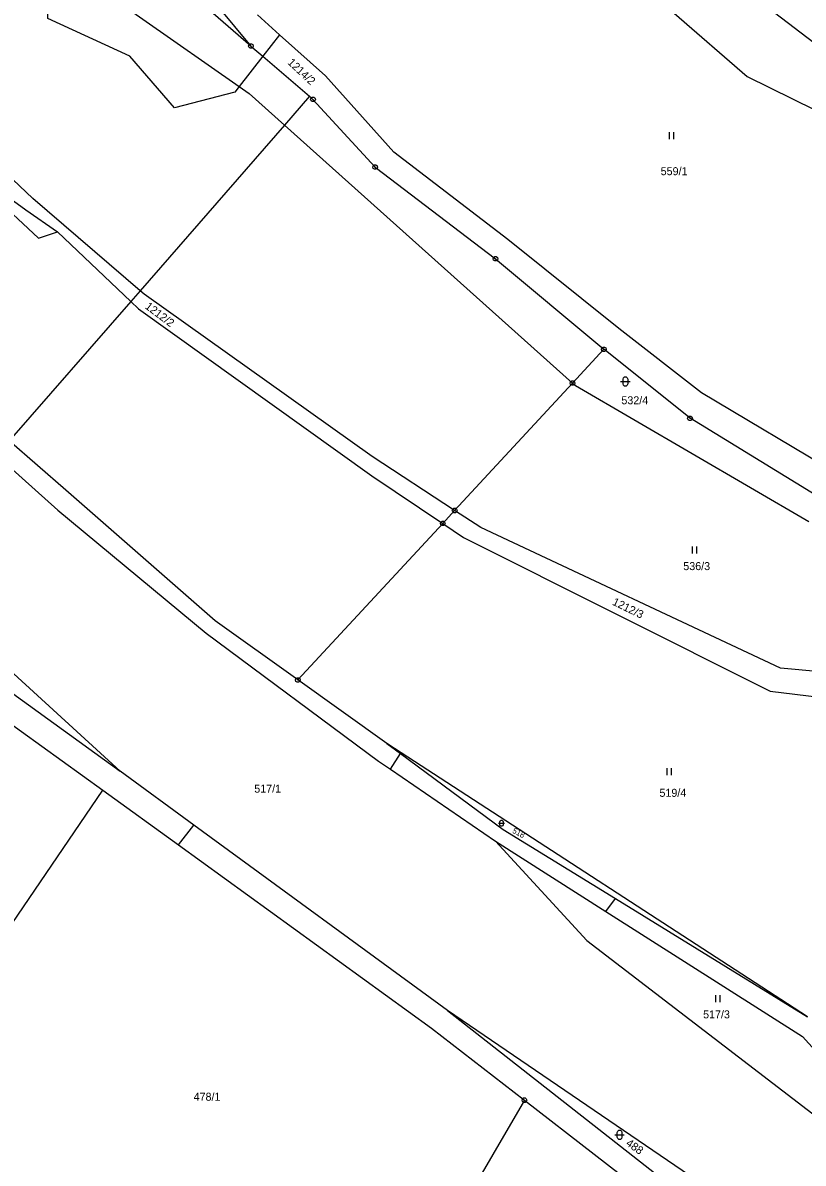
# Model space of a CAD drawing. Extents: x -694465 to -690527, y -983694 to -978978.
# Drawn here: x -692006.8 to -691841.2, y -980787.1 to -980544.9 of the extents above; entities that cross this region are included whole.
import ezdxf

# ---------------------------------------------------------------- set-up
doc = ezdxf.new("R2010")
doc.units = 0
for name, color, linetype in [('Vrstva 1', 7, 'Continuous'), ('Vrstva 18', 7, 'Continuous'), ('Vrstva 24', 7, 'Continuous'), ('Vrstva 25', 7, 'Continuous')]:
    doc.layers.add(name, color=color, linetype=linetype)

msp = doc.modelspace()

# ---------------------------------------------------------------- linework, layer by layer
at = {"layer": 'Vrstva 1'}
for points in [[(-691958.42, -980549.84), (-692001.19, -980512.68)], [(-691871.44, -980524.24), (-691814.85, -980567.53)], [(-692001.777, -980529.752), (-691960.885, -980558.451)], [(-691961.83, -980559.667), (-691974.647, -980562.961), (-691984.109, -980551.967), (-692001.508, -980544.026), (-692001.777, -980529.752)], [(-691884.05, -980529.31), (-691853.08, -980556.33)], [(-691968.46, -980537.69), (-691958.42, -980549.84)], [(-691952.338, -980547.456), (-691957.06, -980543.23)], [(-691952.338, -980547.456), (-691955.886, -980552.02)], [(-691942.57, -980556.2), (-691952.338, -980547.456)], [(-691958.42, -980549.84), (-691955.886, -980552.02)], [(-691955.886, -980552.02), (-691960.885, -980558.451)], [(-691955.886, -980552.02), (-691945.999, -980560.526)], [(-691928.07, -980572.37), (-691942.57, -980556.2)], [(-691853.08, -980556.33), (-691733.07, -980615.47)], [(-691960.885, -980558.451), (-691961.83, -980559.667)], [(-691960.885, -980558.451), (-691958.82, -980559.9)], [(-691958.82, -980559.9), (-691951.311, -980566.629)], [(-691945.999, -980560.526), (-691951.311, -980566.629)], [(-691945.999, -980560.526), (-691945.25, -980561.17)], [(-691945.25, -980561.17), (-691932.06, -980575.55)], [(-691951.311, -980566.629), (-691981.944, -980601.819)], [(-691951.311, -980566.629), (-691890.16, -980621.43)], [(-692004.74, -980582.2), (-692018.83, -980568.84)], [(-692023.24, -980572.26), (-692003.51, -980590.63)], [(-692023.24, -980572.26), (-692006.22, -980584.6)], [(-691903.86, -980590.92), (-691928.07, -980572.37)], [(-691932.06, -980575.55), (-691906.52, -980595.02)], [(-691981.944, -980601.819), (-692004.74, -980582.2)], [(-692006.22, -980584.6), (-691999.47, -980589.28)], [(-692003.51, -980590.63), (-691999.47, -980589.28)], [(-691999.47, -980589.28), (-691983.92, -980604.089)], [(-691880.3, -980609.85), (-691903.86, -980590.92)], [(-691906.52, -980595.02), (-691883.53, -980614.26)], [(-691981.944, -980601.819), (-691983.92, -980604.089)], [(-691981.06, -980602.58), (-691981.944, -980601.819)], [(-691932.66, -980637.04), (-691981.06, -980602.58)], [(-691983.92, -980604.089), (-692009.701, -980633.706)], [(-691983.92, -980604.089), (-691982.26, -980605.67)], [(-691982.26, -980605.67), (-691932.76, -980641.12)], [(-691862.78, -980623.53), (-691880.3, -980609.85)], [(-691883.53, -980614.26), (-691890.16, -980621.43)], [(-691865.23, -980628.91), (-691883.53, -980614.26)], [(-692029.07, -980621.87), (-691999.37, -980648.39)], [(-691890.16, -980621.43), (-691915.18, -980648.5)], [(-691890.16, -980621.43), (-691889.56, -980621.96)], [(-691889.56, -980621.96), (-691839.98, -980650.85)], [(-691833.6, -980640.93), (-691862.78, -980623.53)], [(-691837.38, -980645.95), (-691865.23, -980628.91)], [(-691997.67, -980644.19), (-692009.701, -980633.706)], [(-691915.18, -980648.5), (-691932.66, -980637.04)], [(-691932.76, -980641.12), (-691917.71, -980651.23)], [(-691966, -980671.95), (-691997.67, -980644.19)], [(-691999.37, -980648.39), (-691967.9, -980674.54)], [(-691915.18, -980648.5), (-691917.71, -980651.23)], [(-691909.65, -980652.13), (-691915.18, -980648.5)], [(-691917.71, -980651.23), (-691948.45, -980684.48)], [(-691917.71, -980651.23), (-691913.3, -980654.2)], [(-691846.01, -980681.98), (-691909.65, -980652.13)], [(-691913.3, -980654.2), (-691848.21, -980686.89)], [(-691948.45, -980684.48), (-691966, -980671.95)], [(-691986.14, -980703.88), (-692018.02, -980674.75)], [(-691967.9, -980674.54), (-691931.33, -980701.7)], [(-692021.07, -980678.68), (-691986.14, -980703.88)], [(-692024.46, -980683), (-691989.84, -980707.87)], [(-691837.55, -980682.74), (-691846.01, -980681.98)], [(-691929.56, -980697.98), (-691948.45, -980684.48)], [(-691848.21, -980686.89), (-691837.77, -980688.16)], [(-691926.545, -980699.94), (-691929.56, -980697.98)], [(-691929.56, -980697.98), (-691926.66, -980700.122)], [(-691840.27, -980756.01), (-691926.545, -980699.94)], [(-691931.33, -980701.7), (-691928.779, -980703.453)], [(-691928.779, -980703.453), (-691926.66, -980700.122)], [(-691926.66, -980700.122), (-691904.87, -980716.22)], [(-691970.538, -980715.286), (-691986.14, -980703.88)], [(-691928.779, -980703.453), (-691906.53, -980718.74)], [(-692032.15, -980770.08), (-691989.84, -980707.87)], [(-691989.84, -980707.87), (-691973.796, -980719.504)], [(-691973.796, -980719.504), (-691970.538, -980715.286)], [(-691916.68, -980754.66), (-691970.538, -980715.286)], [(-691904.87, -980716.22), (-691881.078, -980730.875)], [(-691906.53, -980718.74), (-691887.11, -980739.82)], [(-691906.53, -980718.74), (-691883.072, -980733.668)], [(-691973.796, -980719.504), (-691920.13, -980758.42)], [(-691883.072, -980733.668), (-691881.078, -980730.875)], [(-691881.078, -980730.875), (-691840.27, -980756.01)], [(-691883.072, -980733.668), (-691841.33, -980760.23)], [(-691887.11, -980739.82), (-691825.76, -980786.91)], [(-691865.33, -980789.75), (-691916.68, -980754.66)], [(-691916.68, -980754.66), (-691867.5, -980793.3)], [(-691920.13, -980758.42), (-691900.38, -980773.73)], [(-691841.33, -980760.23), (-691822.35, -980781.23)], [(-691900.38, -980773.73), (-691920.05, -980807.52)], [(-691900.38, -980773.73), (-691870.78, -980796.66)]]:
    msp.add_lwpolyline(points, dxfattribs=at)
at = {"layer": 'Vrstva 24'}
for points in [[(-691958.266, -980549.364), (-691958.016, -980549.546), (-691957.92, -980549.84), (-691958.016, -980550.134), (-691958.266, -980550.316), (-691958.574, -980550.316), (-691958.824, -980550.134), (-691958.92, -980549.84), (-691958.824, -980549.546), (-691958.574, -980549.364)], [(-691945.096, -980560.694), (-691944.846, -980560.876), (-691944.75, -980561.17), (-691944.846, -980561.464), (-691945.096, -980561.646), (-691945.404, -980561.646), (-691945.654, -980561.464), (-691945.75, -980561.17), (-691945.654, -980560.876), (-691945.404, -980560.694)], [(-691931.906, -980575.074), (-691931.656, -980575.256), (-691931.56, -980575.55), (-691931.656, -980575.844), (-691931.906, -980576.026), (-691932.214, -980576.026), (-691932.464, -980575.844), (-691932.56, -980575.55), (-691932.464, -980575.256), (-691932.214, -980575.074)], [(-691906.366, -980594.544), (-691906.116, -980594.726), (-691906.02, -980595.02), (-691906.116, -980595.314), (-691906.366, -980595.496), (-691906.674, -980595.496), (-691906.924, -980595.314), (-691907.02, -980595.02), (-691906.924, -980594.726), (-691906.674, -980594.544)], [(-691883.376, -980613.784), (-691883.126, -980613.966), (-691883.03, -980614.26), (-691883.126, -980614.554), (-691883.376, -980614.736), (-691883.684, -980614.736), (-691883.934, -980614.554), (-691884.03, -980614.26), (-691883.934, -980613.966), (-691883.684, -980613.784)], [(-691890.006, -980620.954), (-691889.756, -980621.136), (-691889.66, -980621.43), (-691889.756, -980621.724), (-691890.006, -980621.906), (-691890.314, -980621.906), (-691890.564, -980621.724), (-691890.66, -980621.43), (-691890.564, -980621.136), (-691890.314, -980620.954)], [(-691865.076, -980628.434), (-691864.826, -980628.616), (-691864.73, -980628.91), (-691864.826, -980629.204), (-691865.076, -980629.386), (-691865.384, -980629.386), (-691865.634, -980629.204), (-691865.73, -980628.91), (-691865.634, -980628.616), (-691865.384, -980628.434)], [(-691915.026, -980648.024), (-691914.776, -980648.206), (-691914.68, -980648.5), (-691914.776, -980648.794), (-691915.026, -980648.976), (-691915.334, -980648.976), (-691915.584, -980648.794), (-691915.68, -980648.5), (-691915.584, -980648.206), (-691915.334, -980648.024)], [(-691917.556, -980650.754), (-691917.306, -980650.936), (-691917.21, -980651.23), (-691917.306, -980651.524), (-691917.556, -980651.706), (-691917.864, -980651.706), (-691918.114, -980651.524), (-691918.21, -980651.23), (-691918.114, -980650.936), (-691917.864, -980650.754)], [(-691948.296, -980684.004), (-691948.046, -980684.186), (-691947.95, -980684.48), (-691948.046, -980684.774), (-691948.296, -980684.956), (-691948.604, -980684.956), (-691948.854, -980684.774), (-691948.95, -980684.48), (-691948.854, -980684.186), (-691948.604, -980684.004)], [(-691900.226, -980773.254), (-691899.976, -980773.436), (-691899.88, -980773.73), (-691899.976, -980774.024), (-691900.226, -980774.206), (-691900.534, -980774.206), (-691900.784, -980774.024), (-691900.88, -980773.73), (-691900.784, -980773.436), (-691900.534, -980773.254)]]:
    msp.add_lwpolyline(points, close=True, dxfattribs=at)
for points in [[(-691958.539, -980549.84), (-691958.3, -980549.84)], [(-691945.369, -980561.17), (-691945.13, -980561.17)], [(-691932.179, -980575.55), (-691931.94, -980575.55)], [(-691906.639, -980595.02), (-691906.4, -980595.02)], [(-691883.649, -980614.26), (-691883.41, -980614.26)], [(-691890.279, -980621.43), (-691890.04, -980621.43)], [(-691865.349, -980628.91), (-691865.11, -980628.91)], [(-691915.299, -980648.5), (-691915.06, -980648.5)], [(-691917.829, -980651.23), (-691917.59, -980651.23)], [(-691948.569, -980684.48), (-691948.33, -980684.48)], [(-691900.499, -980773.73), (-691900.26, -980773.73)]]:
    msp.add_lwpolyline(points, dxfattribs=at)
at = {"layer": 'Vrstva 25'}
for points in [[(-691869.63, -980568.11), (-691869.63, -980569.61)], [(-691868.63, -980569.61), (-691868.63, -980568.11)], [(-691879.95, -980621.08), (-691877.95, -980621.08)], [(-691864.75, -980656.15), (-691864.75, -980657.65)], [(-691863.75, -980657.65), (-691863.75, -980656.15)], [(-691870.15, -980703.19), (-691870.15, -980704.69)], [(-691869.15, -980704.69), (-691869.15, -980703.19)], [(-691905.91, -980714.9), (-691904.57, -980714.9)], [(-691859.85, -980751.4), (-691859.85, -980752.9)], [(-691858.85, -980752.9), (-691858.85, -980751.4)], [(-691881.17, -980781.07), (-691879.17, -980781.07)]]:
    msp.add_lwpolyline(points, dxfattribs=at)
for points in [[(-691879.45, -980620.58), (-691879.355, -980620.286), (-691879.105, -980620.104), (-691878.795, -980620.104), (-691878.545, -980620.286), (-691878.45, -980620.58), (-691878.45, -980621.58), (-691878.545, -980621.874), (-691878.795, -980622.056), (-691879.105, -980622.056), (-691879.355, -980621.874), (-691879.45, -980621.58)], [(-691905.575, -980714.565), (-691905.511, -980714.368), (-691905.344, -980714.246), (-691905.136, -980714.246), (-691904.969, -980714.368), (-691904.905, -980714.565), (-691904.905, -980715.235), (-691904.969, -980715.432), (-691905.136, -980715.554), (-691905.344, -980715.554), (-691905.511, -980715.432), (-691905.575, -980715.235)], [(-691880.67, -980780.57), (-691880.575, -980780.276), (-691880.325, -980780.094), (-691880.015, -980780.094), (-691879.765, -980780.276), (-691879.67, -980780.57), (-691879.67, -980781.57), (-691879.765, -980781.864), (-691880.015, -980782.046), (-691880.325, -980782.046), (-691880.575, -980781.864), (-691880.67, -980781.57)]]:
    msp.add_lwpolyline(points, close=True, dxfattribs=at)

# ---------------------------------------------------------------- texts
at = {"layer": 'Vrstva 18'}
for s, height, rotation, p in [('1214/2', 1.7, 316.78836, (-691950.774, -980553.509)), ('1212/2', 1.7, 323.0909, (-691981.046, -980605.44)), ('1212/3', 1.7, 333.9198, (-691881.857, -980668.443)), ('518', 1.2, 332.08634, (-691903.052, -980716.868)), ('488', 1.7, 324.92437, (-691878.988, -980783.2))]:
    msp.add_text(s, height=height, rotation=rotation, dxfattribs=at).set_placement(p)
for s, p in [('559/1', (-691871.453, -980577.28)), ('532/4', (-691879.793, -980625.93)), ('536/3', (-691866.653, -980661.15)), ('517/1', (-691957.714, -980708.42)), ('519/4', (-691871.713, -980709.3)), ('517/3', (-691862.449, -980756.35)), ('478/1', (-691970.582, -980773.85))]:
    msp.add_text(s, height=1.7, dxfattribs=at).set_placement(p)

doc.saveas('drawing.dxf')
